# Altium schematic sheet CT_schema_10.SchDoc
size 308 x 210 mm
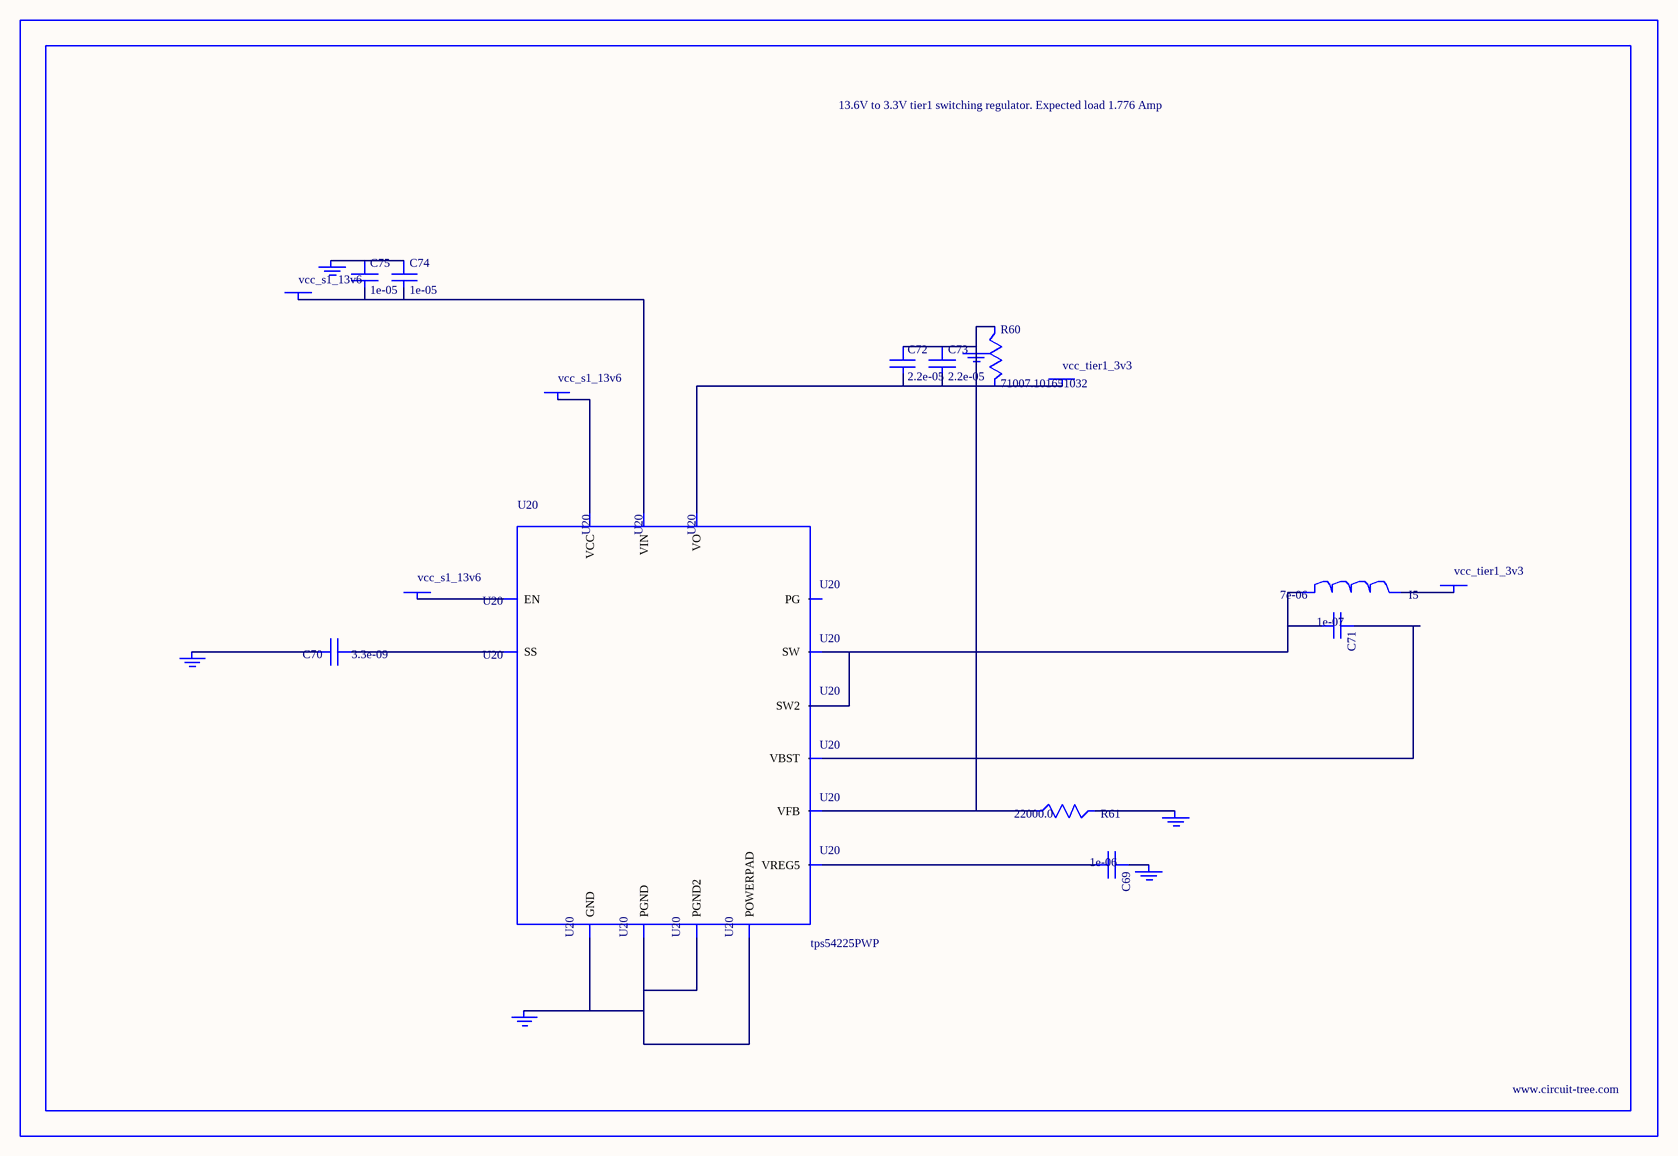
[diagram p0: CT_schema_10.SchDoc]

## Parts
BORDER9  (no value)
C69  1e-06  [C0603]
C70  3.3e-09  [C0402]
C71  1e-07  [C0402]
C72  2.2e-05  [C1210]
C73  2.2e-05  [C1210]
C74  1e-05  [C1206]
C75  1e-05  [C1206]
GND_INSTANCE_9_0  (no value)
GND_INSTANCE_9_1  (no value)
GND_INSTANCE_9_2  (no value)
GND_INSTANCE_9_3  (no value)
GND_INSTANCE_9_4  (no value)
GND_INSTANCE_9_5  (no value)
I5  7e-06  [DR1040]
POWER_INSTANCE_9_0  vcc_tier1_3v3
POWER_INSTANCE_9_1  vcc_s1_13v6
POWER_INSTANCE_9_2  vcc_tier1_3v3
POWER_INSTANCE_9_3  vcc_s1_13v6
POWER_INSTANCE_9_4  vcc_s1_13v6
R60  71007.101651032  [R0603]
R61  22000.0  [R0603]
U20  tps54225PWP  [HTSSOP14]

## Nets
NetC69_1: C69.1 GND_INSTANCE_9_2.0(GND)
NetC69_2: C69.2 U20.3(VREG5)
NetC70_1: C70.1 U20.4(SS)
NetC70_2: C70.2 GND_INSTANCE_9_3.0(GND)
NetC71_1: C71.1 U20.12(VBST)
NetC71_2: C71.2 I5.1 U20.10(SW) U20.11(SW2)
NetC72_1: C72.1 C73.1 GND_INSTANCE_9_0.0(GND) R60.1 R61.1 U20.2(VFB)
NetC72_2: C72.2 C73.2 POWER_INSTANCE_9_0.0(PWR) R60.2 U20.1(VO)
NetC74_1: C74.1 C75.1 GND_INSTANCE_9_5.0(GND)
NetC74_2: C74.2 C75.2 POWER_INSTANCE_9_3.0(PWR) U20.13(VIN)
NetGND_INSTANCE_9_1_0: GND_INSTANCE_9_1.0(GND) R61.2
NetGND_INSTANCE_9_4_0: GND_INSTANCE_9_4.0(GND) U20.5(GND) U20.8(PGND) U20.9(PGND2) U20.15(POWERPAD)
NetI5_2: I5.2 POWER_INSTANCE_9_2.0(PWR)
NetPOWER_INSTANCE_9_1_0: POWER_INSTANCE_9_1.0(PWR) U20.7(EN)
NetPOWER_INSTANCE_9_4_0: POWER_INSTANCE_9_4.0(PWR) U20.14(VCC)

Not connected (* = marked no-connect by the designer): U20 6(PG)

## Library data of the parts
BORDER9 = BORDER_PAGE9
C69 = C0603C105K3RACTU
C70 = C0402C332K3RAC
C71 = C0402C104K3RACTU
C72 C73 = GRM32ER61E226ME15L
C74 C75 = C1206C106K3RACTU
GND_INSTANCE_9_0-GND_INSTANCE_9_5 = GND
I5 = DR1040-7R0-R
POWER_INSTANCE_9_0-POWER_INSTANCE_9_4 = PWR
R60 = R60
R61 = RC0603JR-0722KL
